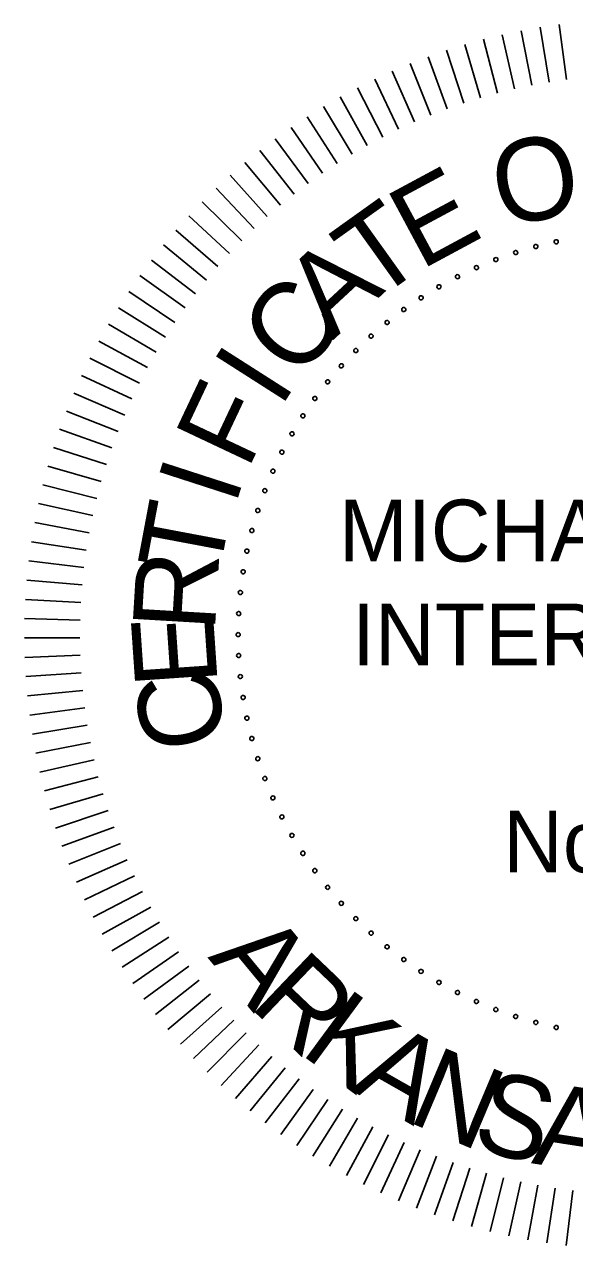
# Model space of a CAD drawing. Extents: x 309348 to 309445, y 336383 to 336484.
# Drawn here: x 309419.519 to 309419.858, y 336456.881 to 336457.634 of the extents above; entities that cross this region are included whole.
import ezdxf

# ---------------------------------------------------------------- set-up
doc = ezdxf.new("R2010")
doc.units = 0
doc.layers.add('R_Border PE', color=7, linetype='Continuous')

msp = doc.modelspace()

# ---------------------------------------------------------------- linework, layer by layer
at = {"layer": 'R_Border PE'}
for points in [[(309419.83183, 336457.5962), (309419.82524, 336457.62977)], [(309419.82524, 336457.62977), (309419.83183, 336457.5962)], [(309419.84251, 336457.59812), (309419.83697, 336457.63189)], [(309419.83697, 336457.63189), (309419.84251, 336457.59812)], [(309419.85323, 336457.59971), (309419.84876, 336457.63363)], [(309419.84876, 336457.63363), (309419.85323, 336457.59971)], [(309419.80025, 336457.58843), (309419.79052, 336457.62123)], [(309419.79052, 336457.62123), (309419.80025, 336457.58843)], [(309419.8107, 336457.59135), (309419.802, 336457.62444)], [(309419.802, 336457.62444), (309419.8107, 336457.59135)], [(309419.82123, 336457.59394), (309419.81358, 336457.62729)], [(309419.81358, 336457.62729), (309419.82123, 336457.59394)], [(309419.77967, 336457.58161), (309419.7679, 336457.61374)], [(309419.7679, 336457.61374), (309419.77967, 336457.58161)], [(309419.78991, 336457.58518), (309419.77915, 336457.61767)], [(309419.77915, 336457.61767), (309419.78991, 336457.58518)], [(309419.76954, 336457.57772), (309419.75677, 336457.60947)], [(309419.75677, 336457.60947), (309419.76954, 336457.57772)], [(309419.74969, 336457.569), (309419.73495, 336457.59988)], [(309419.73495, 336457.59988), (309419.74969, 336457.569)], [(309419.75955, 336457.57352), (309419.74578, 336457.60484)], [(309419.74578, 336457.60484), (309419.75955, 336457.57352)], [(309419.73998, 336457.56417), (309419.72427, 336457.59457)], [(309419.72427, 336457.59457), (309419.73998, 336457.56417)], [(309419.72103, 336457.55362), (309419.70345, 336457.58298)], [(309419.70345, 336457.58298), (309419.72103, 336457.55362)], [(309419.73042, 336457.55905), (309419.71377, 336457.58894)], [(309419.71377, 336457.58894), (309419.73042, 336457.55905)], [(309419.71182, 336457.5479), (309419.69332, 336457.57669)], [(309419.69332, 336457.57669), (309419.71182, 336457.5479)], [(309419.70279, 336457.5419), (309419.6834, 336457.57009)], [(309419.6834, 336457.57009), (309419.70279, 336457.5419)], [(309419.69395, 336457.53561), (309419.67368, 336457.56318)], [(309419.68531, 336457.52905), (309419.66419, 336457.55597)], [(309419.66419, 336457.55597), (309419.68531, 336457.52905)], [(309419.67689, 336457.52223), (309419.65493, 336457.54847)], [(309419.65493, 336457.54847), (309419.67689, 336457.52223)], [(309419.66868, 336457.51514), (309419.64591, 336457.54068)], [(309419.64591, 336457.54068), (309419.66868, 336457.51514)], [(309419.6607, 336457.5078), (309419.63714, 336457.53261)], [(309419.63714, 336457.53261), (309419.6607, 336457.5078)], [(309419.65296, 336457.50021), (309419.62863, 336457.52427)], [(309419.62863, 336457.52427), (309419.65296, 336457.50021)], [(309419.64545, 336457.49238), (309419.62038, 336457.51566)], [(309419.62038, 336457.51566), (309419.64545, 336457.49238)], [(309419.6382, 336457.48431), (309419.61241, 336457.5068)], [(309419.61241, 336457.5068), (309419.6382, 336457.48431)], [(309419.6312, 336457.47603), (309419.60472, 336457.49769)], [(309419.60472, 336457.49769), (309419.6312, 336457.47603)], [(309419.62447, 336457.46753), (309419.59732, 336457.48835)], [(309419.59732, 336457.48835), (309419.62447, 336457.46753)], [(309419.61801, 336457.45882), (309419.59021, 336457.47878)], [(309419.59021, 336457.47878), (309419.61801, 336457.45882)], [(309419.61182, 336457.44991), (309419.58341, 336457.46899)], [(309419.58341, 336457.46899), (309419.61182, 336457.44991)], [(309419.60592, 336457.44082), (309419.57692, 336457.45899)], [(309419.57692, 336457.45899), (309419.60592, 336457.44082)], [(309419.6003, 336457.43154), (309419.57075, 336457.44879)], [(309419.57075, 336457.44879), (309419.6003, 336457.43154)], [(309419.59498, 336457.42209), (309419.56491, 336457.43841)], [(309419.56491, 336457.43841), (309419.59498, 336457.42209)], [(309419.58996, 336457.41248), (309419.55939, 336457.42784)], [(309419.55939, 336457.42784), (309419.58996, 336457.41248)], [(309419.58524, 336457.40271), (309419.5542, 336457.41711)], [(309419.5542, 336457.41711), (309419.58524, 336457.40271)], [(309419.58084, 336457.3928), (309419.54936, 336457.40622)], [(309419.54936, 336457.40622), (309419.58084, 336457.3928)], [(309419.57674, 336457.38276), (309419.54486, 336457.39518)], [(309419.54486, 336457.39518), (309419.57674, 336457.38276)], [(309419.57297, 336457.3726), (309419.54071, 336457.38401)], [(309419.54071, 336457.38401), (309419.57297, 336457.3726)], [(309419.56951, 336457.36232), (309419.53691, 336457.37271)], [(309419.53691, 336457.37271), (309419.56951, 336457.36232)], [(309419.56638, 336457.35193), (309419.53347, 336457.3613)], [(309419.53347, 336457.3613), (309419.56638, 336457.35193)], [(309419.56358, 336457.34146), (309419.53039, 336457.34978)], [(309419.53039, 336457.34978), (309419.56358, 336457.34146)], [(309419.5611, 336457.3309), (309419.52767, 336457.33818)], [(309419.52767, 336457.33818), (309419.5611, 336457.3309)], [(309419.55896, 336457.32027), (309419.52532, 336457.32649)], [(309419.52532, 336457.32649), (309419.55896, 336457.32027)], [(309419.55716, 336457.30957), (309419.52333, 336457.31474)], [(309419.52333, 336457.31474), (309419.55716, 336457.30957)], [(309419.55569, 336457.29883), (309419.52172, 336457.30293)], [(309419.52172, 336457.30293), (309419.55569, 336457.29883)], [(309419.55456, 336457.28804), (309419.52048, 336457.29107)], [(309419.52048, 336457.29107), (309419.55456, 336457.28804)], [(309419.55377, 336457.27723), (309419.51961, 336457.27919)], [(309419.51961, 336457.27919), (309419.55377, 336457.27723)], [(309419.55332, 336457.26639), (309419.51911, 336457.26728)], [(309419.51911, 336457.26728), (309419.55332, 336457.26639)], [(309419.55321, 336457.25555), (309419.51899, 336457.25536)], [(309419.51899, 336457.25536), (309419.55321, 336457.25555)], [(309419.55344, 336457.24471), (309419.51925, 336457.24344)], [(309419.51925, 336457.24344), (309419.55344, 336457.24471)], [(309419.55401, 336457.23388), (309419.51987, 336457.23154)], [(309419.51987, 336457.23154), (309419.55401, 336457.23388)], [(309419.55492, 336457.22307), (309419.52088, 336457.21966)], [(309419.52088, 336457.21966), (309419.55492, 336457.22307)], [(309419.55617, 336457.2123), (309419.52225, 336457.20782)], [(309419.52225, 336457.20782), (309419.55617, 336457.2123)], [(309419.55776, 336457.20157), (309419.524, 336457.19603)], [(309419.524, 336457.19603), (309419.55776, 336457.20157)], [(309419.55969, 336457.1909), (309419.52611, 336457.1843)], [(309419.52611, 336457.1843), (309419.55969, 336457.1909)], [(309419.56194, 336457.18029), (309419.52859, 336457.17264)], [(309419.52859, 336457.17264), (309419.56194, 336457.18029)], [(309419.56453, 336457.16976), (309419.53144, 336457.16107)], [(309419.53144, 336457.16107), (309419.56453, 336457.16976)], [(309419.56745, 336457.15932), (309419.53465, 336457.14959)], [(309419.53465, 336457.14959), (309419.56745, 336457.15932)], [(309419.5707, 336457.14897), (309419.53822, 336457.13822)], [(309419.53822, 336457.13822), (309419.5707, 336457.14897)], [(309419.57427, 336457.13873), (309419.54214, 336457.12696)], [(309419.54214, 336457.12696), (309419.57427, 336457.13873)], [(309419.57816, 336457.12861), (309419.54642, 336457.11584)], [(309419.54642, 336457.11584), (309419.57816, 336457.12861)], [(309419.58237, 336457.11861), (309419.55104, 336457.10485)], [(309419.55104, 336457.10485), (309419.58237, 336457.11861)], [(309419.58688, 336457.10876), (309419.556, 336457.09401)], [(309419.556, 336457.09401), (309419.58688, 336457.10876)], [(309419.59171, 336457.09904), (309419.56131, 336457.08334)], [(309419.56131, 336457.08334), (309419.59171, 336457.09904)], [(309419.59684, 336457.08949), (309419.56694, 336457.07284)], [(309419.56694, 336457.07284), (309419.59684, 336457.08949)], [(309419.60226, 336457.0801), (309419.57291, 336457.06252)], [(309419.57291, 336457.06252), (309419.60226, 336457.0801)], [(309419.60798, 336457.07088), (309419.57919, 336457.05239)], [(309419.57919, 336457.05239), (309419.60798, 336457.07088)], [(309419.61398, 336457.06185), (309419.58579, 336457.04246)], [(309419.58579, 336457.04246), (309419.61398, 336457.06185)], [(309419.62027, 336457.05302), (309419.5927, 336457.03275)], [(309419.5927, 336457.03275), (309419.62027, 336457.05302)], [(309419.62683, 336457.04438), (309419.59991, 336457.02326)], [(309419.59991, 336457.02326), (309419.62683, 336457.04438)], [(309419.63365, 336457.03595), (309419.60741, 336457.014)], [(309419.60741, 336457.014), (309419.63365, 336457.03595)], [(309419.64074, 336457.02775), (309419.6152, 336457.00498)], [(309419.6152, 336457.00498), (309419.64074, 336457.02775)], [(309419.64809, 336457.01977), (309419.62327, 336456.99621)], [(309419.62327, 336456.99621), (309419.64809, 336457.01977)], [(309419.65568, 336457.01202), (309419.63162, 336456.98769)], [(309419.63162, 336456.98769), (309419.65568, 336457.01202)], [(309419.66351, 336457.00452), (309419.64022, 336456.97944)], [(309419.64022, 336456.97944), (309419.66351, 336457.00452)], [(309419.64908, 336456.97147), (309419.67157, 336456.99726)], [(309419.67157, 336456.99726), (309419.64908, 336456.97147)], [(309419.65819, 336456.96378), (309419.67985, 336456.99027)], [(309419.67985, 336456.99027), (309419.65819, 336456.96378)], [(309419.66753, 336456.95638), (309419.68835, 336456.98353)], [(309419.68835, 336456.98353), (309419.66753, 336456.95638)], [(309419.6771, 336456.94928), (309419.69706, 336456.97707)], [(309419.69706, 336456.97707), (309419.6771, 336456.94928)], [(309419.68689, 336456.94248), (309419.70597, 336456.97089)], [(309419.70597, 336456.97089), (309419.68689, 336456.94248)], [(309419.69689, 336456.93599), (309419.71507, 336456.96498)], [(309419.71507, 336456.96498), (309419.69689, 336456.93599)], [(309419.70709, 336456.92982), (309419.72434, 336456.95937)], [(309419.72434, 336456.95937), (309419.70709, 336456.92982)], [(309419.71748, 336456.92397), (309419.73379, 336456.95405)], [(309419.73379, 336456.95405), (309419.71748, 336456.92397)], [(309419.72804, 336456.91845), (309419.74341, 336456.94903)], [(309419.74341, 336456.94903), (309419.72804, 336456.91845)], [(309419.73877, 336456.91327), (309419.75317, 336456.94431)], [(309419.75317, 336456.94431), (309419.73877, 336456.91327)], [(309419.74966, 336456.90842), (309419.76308, 336456.9399)], [(309419.76308, 336456.9399), (309419.74966, 336456.90842)], [(309419.7607, 336456.90392), (309419.77312, 336456.93581)], [(309419.77312, 336456.93581), (309419.7607, 336456.90392)], [(309419.77188, 336456.89977), (309419.78329, 336456.93203)], [(309419.78329, 336456.93203), (309419.77188, 336456.89977)], [(309419.78317, 336456.89598), (309419.79357, 336456.92858)], [(309419.79357, 336456.92858), (309419.78317, 336456.89598)], [(309419.79459, 336456.89253), (309419.80395, 336456.92545)], [(309419.80395, 336456.92545), (309419.79459, 336456.89253)], [(309419.8061, 336456.88945), (309419.81442, 336456.92264)], [(309419.81442, 336456.92264), (309419.8061, 336456.88945)], [(309419.8177, 336456.88674), (309419.82498, 336456.92017)], [(309419.82498, 336456.92017), (309419.8177, 336456.88674)], [(309419.82939, 336456.88438), (309419.83561, 336456.91803)], [(309419.83561, 336456.91803), (309419.82939, 336456.88438)], [(309419.84114, 336456.8824), (309419.84631, 336456.91623)], [(309419.84631, 336456.91623), (309419.84114, 336456.8824)], [(309419.85295, 336456.88079), (309419.85705, 336456.91476)], [(309419.85705, 336456.91476), (309419.85295, 336456.88079)]]:
    msp.add_lwpolyline(points, dxfattribs=at)
for centre, start, end in [((309419.84692, 336457.49969), 12, 192), ((309419.84692, 336457.49969), 192, 12), ((309419.82189, 336457.49298), 18, 198), ((309419.82189, 336457.49298), 198, 18), ((309419.83432, 336457.49666), 15, 195), ((309419.83432, 336457.49666), 195, 15), ((309419.79769, 336457.48369), 24, 204), ((309419.80967, 336457.48865), 21, 201), ((309419.80967, 336457.48865), 201, 21), ((309419.78599, 336457.47811), 27, 207), ((309419.78599, 336457.47811), 207, 27), ((309419.79769, 336457.48369), 204, 24), ((309419.7746, 336457.47192), 30, 210), ((309419.7746, 336457.47192), 210, 30), ((309419.76354, 336457.46515), 33, 213), ((309419.76354, 336457.46515), 213, 33), ((309419.75286, 336457.45781), 36, 216), ((309419.75286, 336457.45781), 216, 36), ((309419.74257, 336457.44991), 39, 219), ((309419.74257, 336457.44991), 219, 39), ((309419.73272, 336457.44149), 42, 222), ((309419.73272, 336457.44149), 222, 42), ((309419.72331, 336457.43257), 45, 225), ((309419.72331, 336457.43257), 225, 45), ((309419.71439, 336457.42317), 48, 228), ((309419.71439, 336457.42317), 228, 48), ((309419.70597, 336457.41331), 51, 231), ((309419.70597, 336457.41331), 231, 51), ((309419.69808, 336457.40302), 54, 234), ((309419.69808, 336457.40302), 234, 54), ((309419.69073, 336457.39234), 57, 237), ((309419.69073, 336457.39234), 237, 57), ((309419.68396, 336457.38129), 60, 240), ((309419.68396, 336457.38129), 240, 60), ((309419.67777, 336457.36989), 63, 243), ((309419.67777, 336457.36989), 243, 63), ((309419.67219, 336457.35819), 66, 246), ((309419.67219, 336457.35819), 246, 66), ((309419.66723, 336457.34621), 69, 249), ((309419.66723, 336457.34621), 249, 69), ((309419.6629, 336457.33399), 72, 252), ((309419.6629, 336457.33399), 252, 72), ((309419.65922, 336457.32156), 75, 255), ((309419.65922, 336457.32156), 255, 75), ((309419.6562, 336457.30896), 78, 258), ((309419.6562, 336457.30896), 258, 78), ((309419.65383, 336457.29621), 81, 261), ((309419.65383, 336457.29621), 261, 81), ((309419.65214, 336457.28336), 84, 264), ((309419.65214, 336457.28336), 264, 84), ((309419.65112, 336457.27043), 87, 267), ((309419.65112, 336457.27043), 267, 87), ((309419.65078, 336457.25747), 90, 270), ((309419.65078, 336457.25747), 270, 90), ((309419.65112, 336457.24451), 93, 273), ((309419.65112, 336457.24451), 273, 93), ((309419.65214, 336457.23159), 96, 276), ((309419.65214, 336457.23159), 276, 96), ((309419.65383, 336457.21874), 99, 279), ((309419.65383, 336457.21874), 279, 99), ((309419.6562, 336457.20599), 102, 282), ((309419.6562, 336457.20599), 282, 102), ((309419.65922, 336457.19338), 105, 285), ((309419.65922, 336457.19338), 285, 105), ((309419.6629, 336457.18095), 108, 288), ((309419.6629, 336457.18095), 288, 108), ((309419.66723, 336457.16873), 111, 291), ((309419.66723, 336457.16873), 291, 111), ((309419.67219, 336457.15676), 114, 294), ((309419.67219, 336457.15676), 294, 114), ((309419.67777, 336457.14506), 117, 297), ((309419.67777, 336457.14506), 297, 117), ((309419.68396, 336457.13366), 120, 300), ((309419.68396, 336457.13366), 300, 120), ((309419.69073, 336457.12261), 123, 303), ((309419.69073, 336457.12261), 303, 123), ((309419.69808, 336457.11192), 126, 306), ((309419.69808, 336457.11192), 306, 126), ((309419.70597, 336457.10164), 129, 309), ((309419.70597, 336457.10164), 309, 129), ((309419.71439, 336457.09178), 132, 312), ((309419.71439, 336457.09178), 312, 132), ((309419.72331, 336457.08238), 135, 315), ((309419.72331, 336457.08238), 315, 135), ((309419.73272, 336457.07345), 138, 318), ((309419.73272, 336457.07345), 318, 138), ((309419.74257, 336457.06503), 141, 321), ((309419.74257, 336457.06503), 321, 141), ((309419.75286, 336457.05714), 144, 324), ((309419.75286, 336457.05714), 324, 144), ((309419.76354, 336457.0498), 147, 327), ((309419.76354, 336457.0498), 327, 147), ((309419.7746, 336457.04303), 150, 330), ((309419.7746, 336457.04303), 330, 150), ((309419.78599, 336457.03684), 153, 333), ((309419.78599, 336457.03684), 333, 153), ((309419.79769, 336457.03126), 156, 336), ((309419.79769, 336457.03126), 336, 156), ((309419.80967, 336457.0263), 159, 339), ((309419.80967, 336457.0263), 339, 159), ((309419.82189, 336457.02197), 162, 342), ((309419.82189, 336457.02197), 342, 162), ((309419.83432, 336457.01829), 165, 345), ((309419.83432, 336457.01829), 345, 165), ((309419.84692, 336457.01526), 168, 348), ((309419.84692, 336457.01526), 348, 168)]:
    msp.add_arc(centre, 0.00127, start, end, dxfattribs=at)

# ---------------------------------------------------------------- texts
for s, rotation, p in [('O', 10.72954, (309419.81255, 336457.50848)), ('E', 28.27898, (309419.7632, 336457.48186)), ('T', 35.57245, (309419.73484, 336457.46218)), ('A', 42.86593, (309419.70903, 336457.4387)), ('C', 50.1594, (309419.68765, 336457.4133)), ('I', 57.45288, (309419.67661, 336457.39631)), ('F', 64.74635, (309419.65666, 336457.35831)), ('I', 72.03983, (309419.64879, 336457.33598)), ('T', 79.33331, (309419.63868, 336457.29219)), ('R', 86.62678, (309419.63636, 336457.2586)), ('E', 93.92026, (309419.63823, 336457.22685)), ('C', 101.21373, (309419.64473, 336457.19151)), ('A', 309.58591, (309419.63173, 336457.05848)), ('R', 316.33564, (309419.65696, 336457.02852)), ('K', 323.64278, (309419.68804, 336456.99967)), ('A', 330.39251, (309419.7198, 336456.97673)), ('N', 337.14224, (309419.75404, 336456.95768)), ('S', 344.44939, (309419.79334, 336456.94176)), ('A', 351.19912, (309419.83118, 336456.9316))]:
    msp.add_text(s, height=0.05082, rotation=rotation, dxfattribs=at).set_placement(p)
for s, height, p in [('MICHAEL BAKER', 0.0381172, (309419.71294, 336457.30253)), (' INTERNATIONAL', 0.0381172, (309419.70681, 336457.23843)), (' No. 1126', 0.038117, (309419.80003, 336457.11081))]:
    msp.add_text(s, height=height, dxfattribs=at).set_placement(p)

doc.saveas('drawing.dxf')
